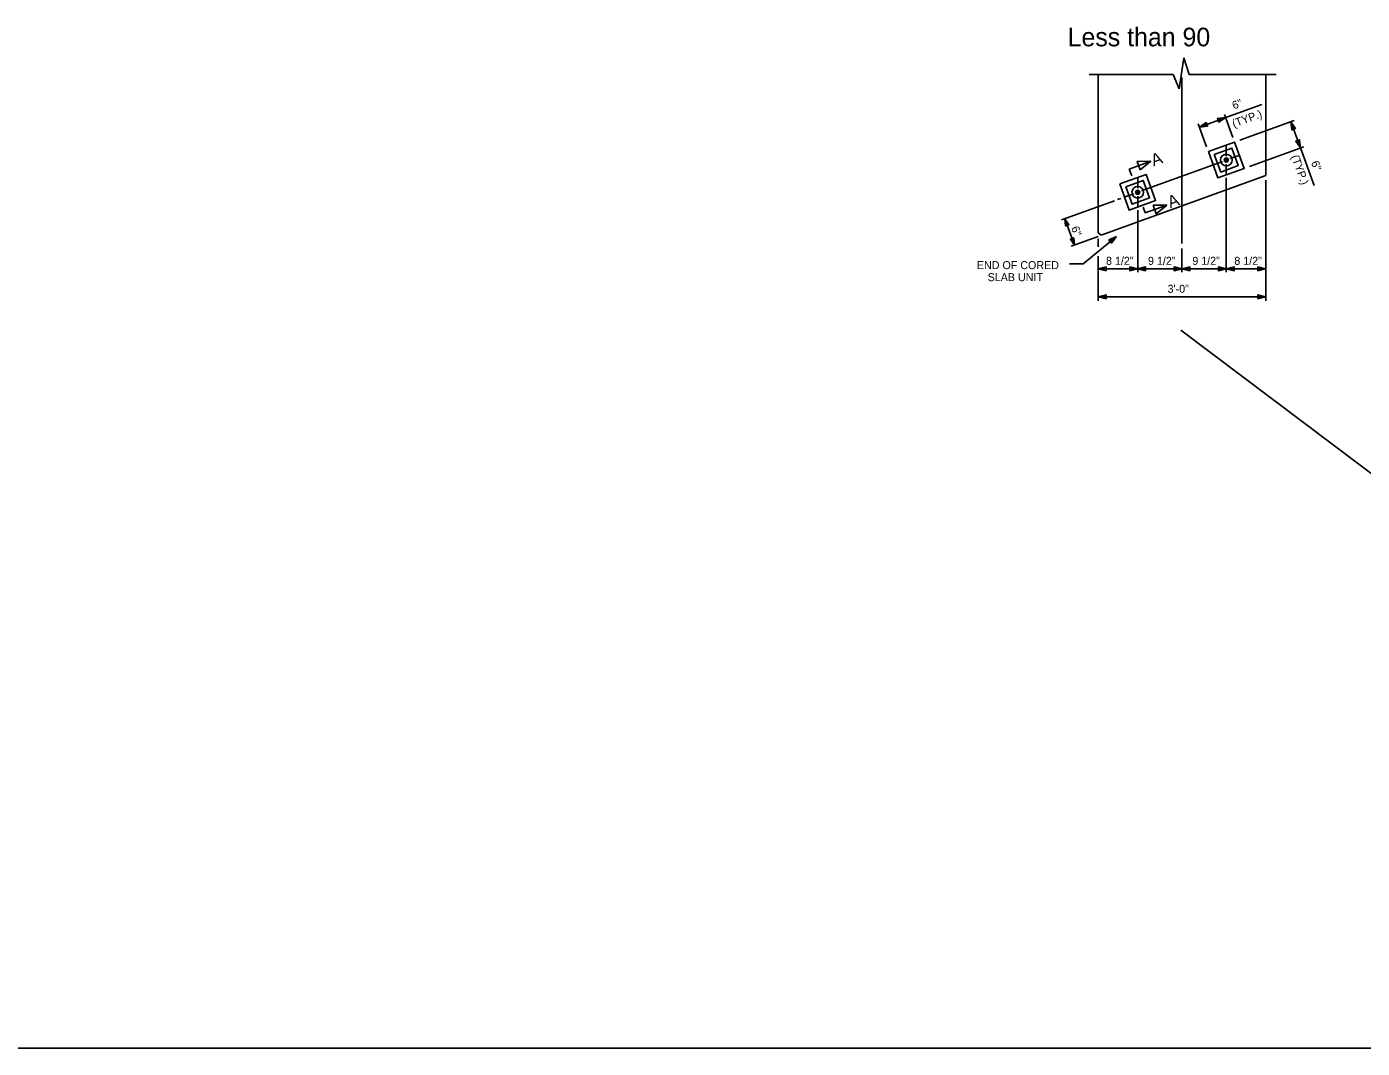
# Model space of a CAD drawing. Extents: x 0 to 177, y -1 to 127.
# Drawn here: x 125.78 to 149.64, y -0.86 to 17.4 of the extents above; entities that cross this region are included whole.
import ezdxf

# ---------------------------------------------------------------- set-up
doc = ezdxf.new("R2010")
doc.units = 0
for name, color, linetype in [('Arrowhead Terminators CELL', 7, 'Continuous'), ('Dimension Lines', 7, 'Continuous'), ('Mis Center Lines', 7, 'Continuous'), ('Plan Sheet', 7, 'Continuous'), ('Rebar Lines', 7, 'Continuous'), ('Structural Steel Lines', 7, 'Continuous'), ('Sup Concrete Girder Lines', 7, 'Continuous'), ('Sup Cored Slab Unit', 7, 'Continuous'), ('Text', 7, 'Continuous'), ('User Information Notes', 7, 'Continuous')]:
    doc.layers.add(name, color=color, linetype=linetype)

msp = doc.modelspace()

# ---------------------------------------------------------------- linework, layer by layer
at = {"layer": 'Arrowhead Terminators CELL'}
for points in [[(147.2, 15.773), (147.078, 15.69), (147.054, 15.757)], [(146.73, 15.602), (146.852, 15.684), (146.876, 15.617)], [(148.362, 15.699), (148.444, 15.577), (148.378, 15.552)], [(148.533, 15.229), (148.451, 15.35), (148.518, 15.375)], [(145.672, 14.837), (145.861, 14.991), (145.618, 14.988)], [(145.903, 14.205), (146.146, 14.208), (145.957, 14.054)], [(145.246, 13.647), (145.159, 13.529), (145.114, 13.584)], [(144.918, 13.068), (145.061, 13.104), (145.061, 13.033)], [(145.627, 13.068), (145.484, 13.033), (145.484, 13.104)], [(145.627, 13.068), (145.769, 13.104), (145.769, 13.033)], [(146.418, 13.068), (146.276, 13.033), (146.276, 13.104)], [(146.418, 13.068), (146.561, 13.104), (146.561, 13.033)], [(147.21, 13.068), (147.068, 13.033), (147.068, 13.104)], [(147.21, 13.068), (147.353, 13.104), (147.353, 13.033)], [(147.918, 13.068), (147.776, 13.033), (147.776, 13.104)], [(144.918, 12.568), (145.061, 12.604), (145.061, 12.533)], [(147.918, 12.568), (147.776, 12.533), (147.776, 12.604)]]:
    msp.add_lwpolyline(points, close=True, dxfattribs=at)
at = {"layer": 'Dimension Lines'}
for p, q in [((147.843, 16.007), (147.2, 15.773)), ((147.2, 15.773), (146.73, 15.602)), ((147.179, 15.83), (147.329, 15.418)), ((146.709, 15.659), (146.859, 15.247)), ((148.425, 15.721), (147.454, 15.368)), ((148.362, 15.699), (148.533, 15.229)), ((147.21, 15.272), (147.21, 15.084)), ((147.455, 15.102), (147.278, 15.038)), ((148.596, 15.252), (147.625, 14.898)), ((148.533, 15.229), (148.777, 14.56)), ((145.476, 14.851), (145.861, 14.991)), ((145.52, 14.73), (145.476, 14.851)), ((147.141, 14.988), (146.965, 14.924)), ((147.21, 14.941), (147.21, 14.754)), ((145.627, 14.696), (145.627, 14.508)), ((147.21, 14.698), (147.21, 13.007)), ((147.918, 14.655), (147.918, 12.497)), ((145.323, 14.326), (145.264, 14.305)), ((145.558, 14.412), (145.382, 14.348)), ((145.627, 14.365), (145.627, 14.178)), ((145.872, 14.526), (145.695, 14.462)), ((145.214, 14.286), (144.267, 13.942)), ((145.627, 14.115), (145.627, 13.007)), ((145.761, 14.068), (145.723, 14.171)), ((145.761, 14.068), (146.146, 14.208)), ((144.325, 13.963), (144.496, 13.493)), ((144.918, 13.647), (144.438, 13.472)), ((145.246, 13.647), (144.651, 13.159)), ((144.918, 13.606), (144.918, 13.463)), ((146.418, 13.433), (146.418, 13.007)), ((144.651, 13.159), (144.406, 13.159)), ((144.918, 13.293), (144.918, 12.497)), ((145.627, 13.068), (144.918, 13.068)), ((146.418, 13.068), (145.627, 13.068)), ((147.21, 13.068), (146.418, 13.068)), ((147.918, 13.068), (147.21, 13.068)), ((147.918, 12.568), (144.918, 12.568))]:
    msp.add_line(p, q, dxfattribs=at)
for points in [[(147.24, 15.024), (147.21, 15.013), (147.21, 15.045)], [(147.18, 15.002), (147.21, 15.013), (147.21, 14.981)], [(145.597, 14.426), (145.627, 14.437), (145.627, 14.405)], [(145.656, 14.448), (145.627, 14.437), (145.627, 14.468)], [(144.368, 13.846), (144.374, 13.848), (144.325, 13.963), (144.38, 13.85), (144.386, 13.852), (144.325, 13.963), (144.392, 13.854), (144.398, 13.856), (144.325, 13.963), (144.339, 13.835), (144.345, 13.837), (144.325, 13.963), (144.351, 13.839), (144.356, 13.841), (144.325, 13.963), (144.362, 13.843), (144.398, 13.856), (144.339, 13.835), (144.325, 13.963), (144.398, 13.856)], [(144.454, 13.611), (144.46, 13.613), (144.496, 13.493), (144.465, 13.615), (144.471, 13.617), (144.496, 13.493), (144.477, 13.619), (144.483, 13.621), (144.496, 13.493), (144.424, 13.6), (144.43, 13.602), (144.496, 13.493), (144.436, 13.604), (144.442, 13.606), (144.496, 13.493), (144.448, 13.609), (144.483, 13.621), (144.424, 13.6), (144.496, 13.493), (144.483, 13.621)]]:
    msp.add_lwpolyline(points, dxfattribs=at)
at = {"layer": 'Mis Center Lines'}
for p, q in [((146.418, 16.49), (146.418, 13.524)), ((145.872, 14.526), (146.965, 14.924))]:
    msp.add_line(p, q, dxfattribs=at)
at = {"layer": 'Plan Sheet'}
msp.add_line((97.47, -0.865), (176.951, -0.865), dxfattribs=at)
at = {"layer": 'Rebar Lines'}
for centre in [(147.21, 15.013), (145.627, 14.437)]:
    msp.add_circle(centre, 0.0365, dxfattribs=at)
at = {"layer": 'Structural Steel Lines'}
for points in [[(146.996, 15.113), (147.11, 14.799), (147.424, 14.913), (147.31, 15.227)], [(145.413, 14.536), (145.527, 14.223), (145.84, 14.337), (145.726, 14.65)]]:
    msp.add_lwpolyline(points, close=True, dxfattribs=at)
at = {"layer": 'Sup Concrete Girder Lines'}
for p, q in [((146.45, 16.839), (146.365, 16.286)), ((146.546, 16.54), (146.45, 16.839)), ((146.259, 16.54), (144.759, 16.54)), ((144.918, 13.709), (144.918, 16.54)), ((146.365, 16.286), (146.259, 16.54)), ((148.099, 16.54), (146.546, 16.54)), ((147.918, 14.739), (147.918, 16.54)), ((147.918, 14.739), (144.977, 13.668)), ((144.918, 13.709), (144.977, 13.668))]:
    msp.add_line(p, q, dxfattribs=at)
for centre in [(147.21, 15.013), (145.627, 14.437)]:
    msp.add_circle(centre, 0.104, dxfattribs=at)
at = {"layer": 'Sup Cored Slab Unit'}
for points in [[(146.89, 15.163), (147.061, 14.693), (147.53, 14.864), (147.359, 15.334)], [(145.306, 14.586), (145.477, 14.116), (145.947, 14.287), (145.776, 14.757)]]:
    msp.add_lwpolyline(points, close=True, dxfattribs=at)
at = {"layer": 'Text'}
for p, q in [((147.918, 14.81), (147.918, 16.26)), ((147.918, 14.81), (147.918, 15.942)), ((147.918, 14.81), (147.918, 15.807)), ((147.918, 14.81), (147.918, 15.72)), ((147.918, 14.81), (147.918, 15.512)), ((147.454, 14.57), (147.361, 14.536)), ((147.079, 14.433), (146.865, 14.355))]:
    msp.add_line(p, q, dxfattribs=at)
at = {"layer": 'User Information Notes'}
for q in [(146.4, 11.974), (153.4, 6.689)]:
    msp.add_line((146.4, 11.974), q, dxfattribs=at)

# ---------------------------------------------------------------- texts
at = {"layer": 'Dimension Lines'}
for p in [(145.911, 14.899), (146.21, 14.15)]:
    msp.add_text('A', height=0.215, rotation=20.0008, dxfattribs=at).set_placement(p)
at = {"layer": 'Text'}
for s, rotation, p in [('6"', 20.0008, (147.345, 15.916)), ('(TYP.)', 20.0008, (147.344, 15.592)), ('(TYP.)', 290.0008, (148.365, 15.076)), ('6"', 290.0008, (148.721, 14.97)), ('6"', 290.0121, (144.435, 13.801))]:
    msp.add_text(s, height=0.143, rotation=rotation, dxfattribs=at).set_placement(p)
for s, p in [('END OF CORED', (142.754, 13.063)), ('8 1/2"', (145.061, 13.14)), ('9 1/2"', (145.811, 13.14)), ('9 1/2"', (146.603, 13.14)), ('8 1/2"', (147.353, 13.14)), ('SLAB UNIT', (142.946, 12.848)), ('3\'-0"', (146.161, 12.64))]:
    msp.add_text(s, height=0.143, dxfattribs=at).set_placement(p)
at = {"layer": 'User Information Notes'}
msp.add_text('Less than 90', height=0.33267, dxfattribs=at).set_placement((144.375, 17.046))

doc.saveas('drawing.dxf')
